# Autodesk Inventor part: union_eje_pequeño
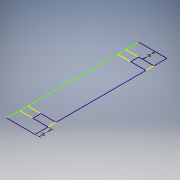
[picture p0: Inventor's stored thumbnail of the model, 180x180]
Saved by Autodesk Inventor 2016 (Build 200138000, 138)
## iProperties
Created: 2017-06
Part Number: union_eje_pequeño
Material: Generic
Document SubType Name: Modeling
Designer: laboratorioesan
Density: 1 g/cm^3
Appearance: Default
Author: laboratorioesan
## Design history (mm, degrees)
sketch "Sketch1"
  geometry: L1 (0, 0)-(30, 0) reference; L2 (0, -18.5)-(0, 0) reference; L3 (30, -18.5)-(0, -18.5) reference; L4 (30, 0)-(30, -18.5) reference; L5 (0, 226.5)-(30, 226.5) reference; L6 (0, 208)-(0, 226.5) reference; L7 (30, 208)-(0, 208) reference; L8 (30, 226.5)-(30, 208) reference; L9 (65, 0)-(65, -18.5) reference; L10 (65, 226.5)-(65, 208) reference; L11 (65, 226.5)-(30, 226.5); L12 (30, 226.5)-(30, 208); L13 (30, 208)-(65, 208); L14 (65, 226.5)-(65, 256.5); L15 (65, 256.5)-(0, 256.5); L16 (0, 256.5)-(0, -48.5); L17 (0, -48.5)-(65, -48.5); L18 (65, -48.5)-(65, -18.5); L19 (65, -18.5)-(30, -18.5); L20 (30, -18.5)-(30, 0); L21 (30, 0)-(65, 0); L22 (65, 208)-(65, 0); L23 (65, 256.5)-(65, 226.5); L24 (65, 226.5)-(30, 226.5)
  constraints: 28 end point, 11 perpendicular, 2 collinear, 1 horizontal, 1 point on line
  dimensions: "d0" = 30 distance of L10.start L14.end; "d1" = 30 distance between parallel lines of L17 L19
  node "Reference1"
  node "Reference2"
  node "Reference3"
  node "Reference4"
